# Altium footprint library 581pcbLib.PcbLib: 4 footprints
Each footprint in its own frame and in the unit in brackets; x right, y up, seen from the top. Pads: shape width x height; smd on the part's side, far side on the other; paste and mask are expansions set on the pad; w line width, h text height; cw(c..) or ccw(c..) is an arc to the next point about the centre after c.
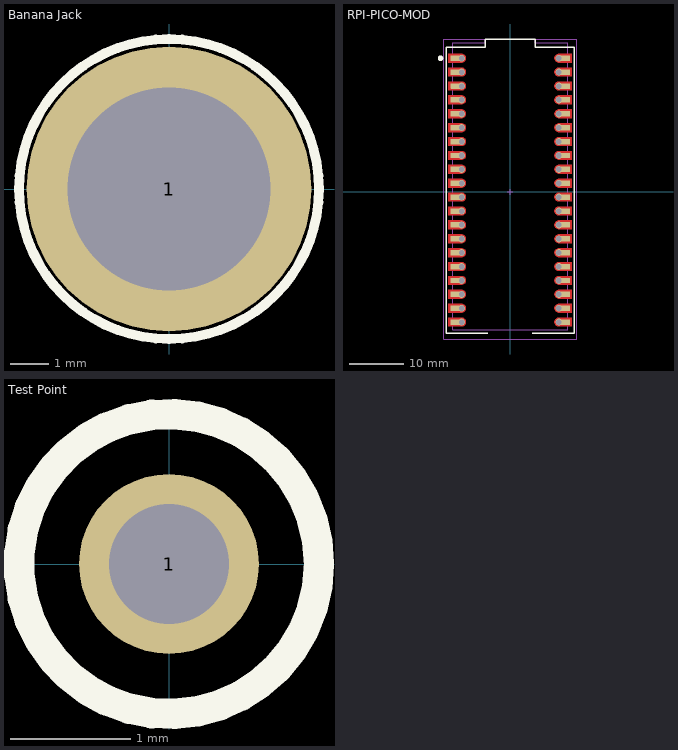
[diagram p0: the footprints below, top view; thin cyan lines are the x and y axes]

## Banana Jack [mm] "575-8"
pads (1):
  round 7.5 hole 5.35: 1(0,0)
Top Overlay:
  circle w0.254: c0,0 r3.95
3D body: height 2.47, standoff 0.1, extent -2.59,-2.65 2.59,2.54
3D body: height 2.46, standoff 0.1, extent -3.932,-3.947 3.937,3.937
3D body: height 9, standoff 0.1, extent -2.59,-2.667 2.59,2.523

## PCBComponent_1 [mm]

## RPI-PICO-MOD [mm] "RASPBERRY PI PICO RP2040 BOARD"
height 1
pads (40):
  rect 2.5x1 smd mask+0.102: 1(-9.69,24.415) 2(-9.69,21.875) 4(-9.69,16.795) 5(-9.69,14.255) 6(-9.69,11.715) 7(-9.69,9.175) 8(-9.69,6.635) 9(-9.69,4.095) 10(-9.69,1.555) 11(-9.69,-0.985) 12(-9.69,-3.525) 13(-9.69,-6.065) 14(-9.69,-8.605) 15(-9.69,-11.145) 16(-9.69,-13.685) 17(-9.69,-16.225) 18(-9.69,-18.765) 19(-9.69,-21.305) 20(-9.69,-23.845)
  rrect25% 2.5x1 smd mask+0.102: 3(-9.69,19.335)
  rect 2.5x1 smd: 21(9.69,-23.845) 22(9.69,-21.305) 23(9.69,-18.765) 24(9.69,-16.225) 25(9.69,-13.685) 26(9.69,-11.145) 27(9.69,-8.605) 28(9.69,-6.065) 29(9.69,-3.525) 30(9.69,-0.985) 31(9.69,1.555) 32(9.69,4.095) 33(9.69,6.635) 34(9.69,9.175) 35(9.69,11.715) 36(9.69,14.255) 37(9.69,16.795) 38(9.69,19.335) 39(9.69,21.875) 40(9.69,24.415)
via 8.89,24.415 diameter 1.27 hole 1.016
via 8.89,24.415 diameter 1.27 hole 1.016
via 8.89,21.875 diameter 1.27 hole 1.016
via 8.89,19.335 diameter 1.27 hole 1.016
via 8.89,16.795 diameter 1.27 hole 1.016
via 8.89,14.255 diameter 1.27 hole 1.016
via 8.89,11.715 diameter 1.27 hole 1.016
via 8.89,9.175 diameter 1.27 hole 1.016
via 8.89,6.635 diameter 1.27 hole 1.016
via 8.89,4.095 diameter 1.27 hole 1.016
via 8.89,1.555 diameter 1.27 hole 1.016
via 8.89,-0.985 diameter 1.27 hole 1.016
via 8.89,-3.525 diameter 1.27 hole 1.016
via 8.89,-6.065 diameter 1.27 hole 1.016
via 8.89,-8.605 diameter 1.27 hole 1.016
via 8.89,-11.145 diameter 1.27 hole 1.016
via 8.89,-13.685 diameter 1.27 hole 1.016
via 8.89,-16.225 diameter 1.27 hole 1.016
via 8.89,-18.765 diameter 1.27 hole 1.016
via 8.89,-21.305 diameter 1.27 hole 1.016
via 8.89,-23.845 diameter 1.27 hole 1.016
via -8.89,24.415 diameter 1.27 hole 1.016
via -8.89,24.415 diameter 1.27 hole 1.016
via -8.89,21.875 diameter 1.27 hole 1.016
via -8.89,19.335 diameter 1.27 hole 1.016
via -8.89,16.795 diameter 1.27 hole 1.016
via -8.89,14.255 diameter 1.27 hole 1.016
via -8.89,11.715 diameter 1.27 hole 1.016
via -8.89,9.175 diameter 1.27 hole 1.016
via -8.89,6.635 diameter 1.27 hole 1.016
via -8.89,4.095 diameter 1.27 hole 1.016
via -8.89,1.555 diameter 1.27 hole 1.016
via -8.89,-0.985 diameter 1.27 hole 1.016
via -8.89,-3.525 diameter 1.27 hole 1.016
via -8.89,-6.065 diameter 1.27 hole 1.016
via -8.89,-8.605 diameter 1.27 hole 1.016
via -8.89,-11.145 diameter 1.27 hole 1.016
via -8.89,-13.685 diameter 1.27 hole 1.016
via -8.89,-16.225 diameter 1.27 hole 1.016
via -8.89,-18.765 diameter 1.27 hole 1.016
via -8.89,-21.305 diameter 1.27 hole 1.016
via -8.89,-23.845 diameter 1.27 hole 1.016
Top Layer:
  region: 11.292,-24.629 11.292,-23.029 8.892,-23.029 8.787,-23.029 8.583,-23.084 8.401,-23.189 8.252,-23.338 8.147,-23.52 8.092,-23.724 8.092,-23.934 8.147,-24.138 8.252,-24.32 8.401,-24.469 8.583,-24.574 8.787,-24.629 8.892,-24.629
  region: 11.292,-22.089 11.292,-20.489 8.892,-20.489 8.787,-20.489 8.583,-20.544 8.401,-20.649 8.252,-20.798 8.147,-20.98 8.092,-21.184 8.092,-21.394 8.147,-21.598 8.252,-21.78 8.401,-21.929 8.583,-22.034 8.787,-22.089 8.892,-22.089
  region: 11.292,-19.549 11.292,-17.949 8.892,-17.949 8.787,-17.949 8.583,-18.004 8.401,-18.109 8.252,-18.258 8.147,-18.44 8.092,-18.644 8.092,-18.854 8.147,-19.058 8.252,-19.24 8.401,-19.389 8.583,-19.494 8.787,-19.549 8.892,-19.549
  region: 11.292,-17.009 11.292,-15.409 8.892,-15.409 8.787,-15.409 8.583,-15.464 8.401,-15.569 8.252,-15.718 8.147,-15.9 8.092,-16.104 8.092,-16.314 8.147,-16.518 8.252,-16.7 8.401,-16.849 8.583,-16.954 8.787,-17.009 8.892,-17.009
  region: 11.292,-14.469 11.292,-12.869 8.892,-12.869 8.787,-12.869 8.583,-12.924 8.401,-13.029 8.252,-13.178 8.147,-13.36 8.092,-13.564 8.092,-13.774 8.147,-13.978 8.252,-14.16 8.401,-14.309 8.583,-14.414 8.787,-14.469 8.892,-14.469
  region: 11.292,-11.929 11.292,-10.329 8.892,-10.329 8.787,-10.329 8.583,-10.384 8.401,-10.489 8.252,-10.638 8.147,-10.82 8.092,-11.024 8.092,-11.234 8.147,-11.438 8.252,-11.62 8.401,-11.769 8.583,-11.874 8.787,-11.929 8.892,-11.929
  region: 11.292,-9.389 11.292,-7.789 8.892,-7.789 8.787,-7.789 8.583,-7.844 8.401,-7.949 8.252,-8.098 8.147,-8.28 8.092,-8.484 8.092,-8.694 8.147,-8.898 8.252,-9.08 8.401,-9.229 8.583,-9.334 8.787,-9.389 8.892,-9.389
  region: 11.292,-6.849 11.292,-5.249 8.892,-5.249 8.787,-5.249 8.583,-5.304 8.401,-5.409 8.252,-5.558 8.147,-5.74 8.092,-5.944 8.092,-6.154 8.147,-6.358 8.252,-6.54 8.401,-6.689 8.583,-6.794 8.787,-6.849 8.892,-6.849
  region: 11.292,-4.309 11.292,-2.709 8.892,-2.709 8.787,-2.709 8.583,-2.764 8.401,-2.869 8.252,-3.018 8.147,-3.2 8.092,-3.404 8.092,-3.614 8.147,-3.818 8.252,-4 8.401,-4.149 8.583,-4.254 8.787,-4.309 8.892,-4.309
  region: 11.292,-1.769 11.292,-0.169 8.892,-0.169 8.787,-0.169 8.583,-0.224 8.401,-0.329 8.252,-0.478 8.147,-0.66 8.092,-0.864 8.092,-1.074 8.147,-1.278 8.252,-1.46 8.401,-1.609 8.583,-1.714 8.787,-1.769 8.892,-1.769
  region: 11.292,0.771 11.292,2.371 8.892,2.371 8.787,2.371 8.583,2.316 8.401,2.211 8.252,2.062 8.147,1.88 8.092,1.676 8.092,1.466 8.147,1.262 8.252,1.08 8.401,0.931 8.583,0.826 8.787,0.771 8.892,0.771
  region: 11.292,3.311 11.292,4.911 8.892,4.911 8.787,4.911 8.583,4.856 8.401,4.751 8.252,4.602 8.147,4.42 8.092,4.216 8.092,4.006 8.147,3.802 8.252,3.62 8.401,3.471 8.583,3.366 8.787,3.311 8.892,3.311
  region: 11.292,5.851 11.292,7.451 8.892,7.451 8.787,7.451 8.583,7.396 8.401,7.291 8.252,7.142 8.147,6.96 8.092,6.756 8.092,6.546 8.147,6.342 8.252,6.16 8.401,6.011 8.583,5.906 8.787,5.851 8.892,5.851
  region: 11.292,8.391 11.292,9.991 8.892,9.991 8.787,9.991 8.583,9.936 8.401,9.831 8.252,9.682 8.147,9.5 8.092,9.296 8.092,9.086 8.147,8.882 8.252,8.7 8.401,8.551 8.583,8.446 8.787,8.391 8.892,8.391
  region: 11.292,10.931 11.292,12.531 8.892,12.531 8.787,12.531 8.583,12.476 8.401,12.371 8.252,12.222 8.147,12.04 8.092,11.836 8.092,11.626 8.147,11.422 8.252,11.24 8.401,11.091 8.583,10.986 8.787,10.931 8.892,10.931
  region: 11.292,13.471 11.292,15.071 8.892,15.071 8.787,15.071 8.583,15.016 8.401,14.911 8.252,14.762 8.147,14.58 8.092,14.376 8.092,14.166 8.147,13.962 8.252,13.78 8.401,13.631 8.583,13.526 8.787,13.471 8.892,13.471
  region: 11.292,16.011 11.292,17.611 8.892,17.611 8.787,17.611 8.583,17.556 8.401,17.451 8.252,17.302 8.147,17.12 8.092,16.916 8.092,16.706 8.147,16.502 8.252,16.32 8.401,16.171 8.583,16.066 8.787,16.011 8.892,16.011
  region: 11.292,18.551 11.292,20.151 8.892,20.151 8.787,20.151 8.583,20.096 8.401,19.991 8.252,19.842 8.147,19.66 8.092,19.456 8.092,19.246 8.147,19.042 8.252,18.86 8.401,18.711 8.583,18.606 8.787,18.551 8.892,18.551
  region: 11.292,21.091 11.292,22.691 8.892,22.691 8.787,22.691 8.583,22.636 8.401,22.531 8.252,22.382 8.147,22.2 8.092,21.996 8.092,21.786 8.147,21.582 8.252,21.4 8.401,21.251 8.583,21.146 8.787,21.091 8.892,21.091
  region: 11.292,23.631 11.292,25.231 8.892,25.231 8.787,25.231 8.583,25.176 8.401,25.071 8.252,24.922 8.147,24.74 8.092,24.536 8.092,24.326 8.147,24.122 8.252,23.94 8.401,23.791 8.583,23.686 8.787,23.631 8.892,23.631
  region: -11.292,23.631 -11.292,25.231 -8.892,25.231 -8.787,25.231 -8.583,25.176 -8.401,25.071 -8.252,24.922 -8.147,24.74 -8.092,24.536 -8.092,24.326 -8.147,24.122 -8.252,23.94 -8.401,23.791 -8.583,23.686 -8.787,23.631 -8.892,23.631
  region: -11.292,21.091 -11.292,22.691 -8.892,22.691 -8.787,22.691 -8.583,22.636 -8.401,22.531 -8.252,22.382 -8.147,22.2 -8.092,21.996 -8.092,21.786 -8.147,21.582 -8.252,21.4 -8.401,21.251 -8.583,21.146 -8.787,21.091 -8.892,21.091
  region: -11.292,18.551 -11.292,20.151 -8.892,20.151 -8.787,20.151 -8.583,20.096 -8.401,19.991 -8.252,19.842 -8.147,19.66 -8.092,19.456 -8.092,19.246 -8.147,19.042 -8.252,18.86 -8.401,18.711 -8.583,18.606 -8.787,18.551 -8.892,18.551
  region: -11.292,16.011 -11.292,17.611 -8.892,17.611 -8.787,17.611 -8.583,17.556 -8.401,17.451 -8.252,17.302 -8.147,17.12 -8.092,16.916 -8.092,16.706 -8.147,16.502 -8.252,16.32 -8.401,16.171 -8.583,16.066 -8.787,16.011 -8.892,16.011
  region: -11.292,13.471 -11.292,15.071 -8.892,15.071 -8.787,15.071 -8.583,15.016 -8.401,14.911 -8.252,14.762 -8.147,14.58 -8.092,14.376 -8.092,14.166 -8.147,13.962 -8.252,13.78 -8.401,13.631 -8.583,13.526 -8.787,13.471 -8.892,13.471
  region: -11.292,10.931 -11.292,12.531 -8.892,12.531 -8.787,12.531 -8.583,12.476 -8.401,12.371 -8.252,12.222 -8.147,12.04 -8.092,11.836 -8.092,11.626 -8.147,11.422 -8.252,11.24 -8.401,11.091 -8.583,10.986 -8.787,10.931 -8.892,10.931
  region: -11.292,8.391 -11.292,9.991 -8.892,9.991 -8.787,9.991 -8.583,9.936 -8.401,9.831 -8.252,9.682 -8.147,9.5 -8.092,9.296 -8.092,9.086 -8.147,8.882 -8.252,8.7 -8.401,8.551 -8.583,8.446 -8.787,8.391 -8.892,8.391
  region: -11.292,5.851 -11.292,7.451 -8.892,7.451 -8.787,7.451 -8.583,7.396 -8.401,7.291 -8.252,7.142 -8.147,6.96 -8.092,6.756 -8.092,6.546 -8.147,6.342 -8.252,6.16 -8.401,6.011 -8.583,5.906 -8.787,5.851 -8.892,5.851
  region: -11.292,3.311 -11.292,4.911 -8.892,4.911 -8.787,4.911 -8.583,4.856 -8.401,4.751 -8.252,4.602 -8.147,4.42 -8.092,4.216 -8.092,4.006 -8.147,3.802 -8.252,3.62 -8.401,3.471 -8.583,3.366 -8.787,3.311 -8.892,3.311
  region: -11.292,0.771 -11.292,2.371 -8.892,2.371 -8.787,2.371 -8.583,2.316 -8.401,2.211 -8.252,2.062 -8.147,1.88 -8.092,1.676 -8.092,1.466 -8.147,1.262 -8.252,1.08 -8.401,0.931 -8.583,0.826 -8.787,0.771 -8.892,0.771
  region: -11.292,-1.769 -11.292,-0.169 -8.892,-0.169 -8.787,-0.169 -8.583,-0.224 -8.401,-0.329 -8.252,-0.478 -8.147,-0.66 -8.092,-0.864 -8.092,-1.074 -8.147,-1.278 -8.252,-1.46 -8.401,-1.609 -8.583,-1.714 -8.787,-1.769 -8.892,-1.769
  region: -11.292,-4.309 -11.292,-2.709 -8.892,-2.709 -8.787,-2.709 -8.583,-2.764 -8.401,-2.869 -8.252,-3.018 -8.147,-3.2 -8.092,-3.404 -8.092,-3.614 -8.147,-3.818 -8.252,-4 -8.401,-4.149 -8.583,-4.254 -8.787,-4.309 -8.892,-4.309
  region: -11.292,-6.849 -11.292,-5.249 -8.892,-5.249 -8.787,-5.249 -8.583,-5.304 -8.401,-5.409 -8.252,-5.558 -8.147,-5.74 -8.092,-5.944 -8.092,-6.154 -8.147,-6.358 -8.252,-6.54 -8.401,-6.689 -8.583,-6.794 -8.787,-6.849 -8.892,-6.849
  region: -11.292,-9.389 -11.292,-7.789 -8.892,-7.789 -8.787,-7.789 -8.583,-7.844 -8.401,-7.949 -8.252,-8.098 -8.147,-8.28 -8.092,-8.484 -8.092,-8.694 -8.147,-8.898 -8.252,-9.08 -8.401,-9.229 -8.583,-9.334 -8.787,-9.389 -8.892,-9.389
  region: -11.292,-11.929 -11.292,-10.329 -8.892,-10.329 -8.787,-10.329 -8.583,-10.384 -8.401,-10.489 -8.252,-10.638 -8.147,-10.82 -8.092,-11.024 -8.092,-11.234 -8.147,-11.438 -8.252,-11.62 -8.401,-11.769 -8.583,-11.874 -8.787,-11.929 -8.892,-11.929
  region: -11.292,-14.469 -11.292,-12.869 -8.892,-12.869 -8.787,-12.869 -8.583,-12.924 -8.401,-13.029 -8.252,-13.178 -8.147,-13.36 -8.092,-13.564 -8.092,-13.774 -8.147,-13.978 -8.252,-14.16 -8.401,-14.309 -8.583,-14.414 -8.787,-14.469 -8.892,-14.469
  region: -11.292,-17.009 -11.292,-15.409 -8.892,-15.409 -8.787,-15.409 -8.583,-15.464 -8.401,-15.569 -8.252,-15.718 -8.147,-15.9 -8.092,-16.104 -8.092,-16.314 -8.147,-16.518 -8.252,-16.7 -8.401,-16.849 -8.583,-16.954 -8.787,-17.009 -8.892,-17.009
  region: -11.292,-19.549 -11.292,-17.949 -8.892,-17.949 -8.787,-17.949 -8.583,-18.004 -8.401,-18.109 -8.252,-18.258 -8.147,-18.44 -8.092,-18.644 -8.092,-18.854 -8.147,-19.058 -8.252,-19.24 -8.401,-19.389 -8.583,-19.494 -8.787,-19.549 -8.892,-19.549
  region: -11.292,-22.089 -11.292,-20.489 -8.892,-20.489 -8.787,-20.489 -8.583,-20.544 -8.401,-20.649 -8.252,-20.798 -8.147,-20.98 -8.092,-21.184 -8.092,-21.394 -8.147,-21.598 -8.252,-21.78 -8.401,-21.929 -8.583,-22.034 -8.787,-22.089 -8.892,-22.089
  region: -11.292,-24.629 -11.292,-23.029 -8.892,-23.029 -8.787,-23.029 -8.583,-23.084 -8.401,-23.189 -8.252,-23.338 -8.147,-23.52 -8.092,-23.724 -8.092,-23.934 -8.147,-24.138 -8.252,-24.32 -8.401,-24.469 -8.583,-24.574 -8.787,-24.629 -8.892,-24.629
Top Overlay:
  circle w0.508: c-12.738,24.415 r0.254
  lines w0.254: -4.102,-25.877 -11.684,-25.877 -11.684,26.416 -4.572,26.416 -4.572,27.94 4.572,27.94 4.572,26.416 11.684,26.416 11.684,-25.877 4.026,-25.877
Mechanical 13:
  lines w0.1: -10.49,-25.208 10.51,-25.208 10.51,27.218 4.572,27.218 4.572,27.94 -3.048,27.94 -4.572,27.94 -4.572,27.218 -10.49,27.218 -10.49,-25.208
Mechanical 15:
  lines w0.05: -0.5,0 0.5,0 ; 0,-0.5 0,0.5 ; -12.192,-26.924 12.192,-26.924 12.192,27.94 -12.192,27.94 -12.192,-26.924
3D body "Raspberry Pi Pico-R3.STEP": height 3.69, standoff 0, extent -10.49,-25.208 10.51,27.218

## Test Point [mm] "Keystone 500(0-4)"
pads (1):
  round 1.5 hole 1: 1(0,0)
Top Overlay:
  circle w0.254: c0,0 r1.25
3D body "User Library-Test Point Keystone - 5004 YELLOW.STEP": height 3.05, standoff -4.57, extent -1.27,-1.27 1.27,1.27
